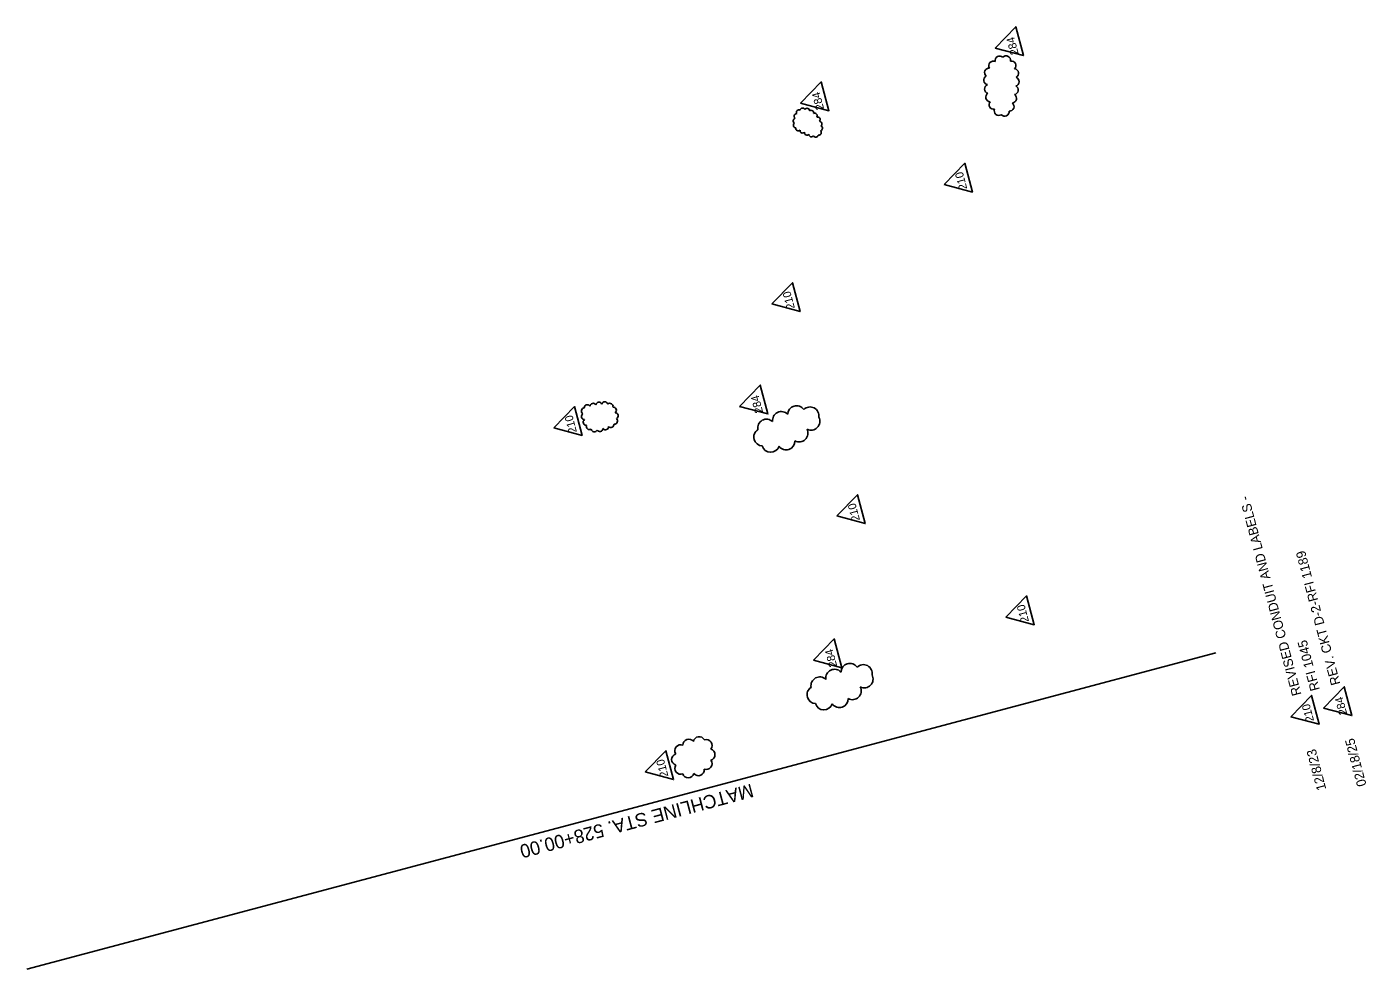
# Model space of a CAD drawing. Extents: x 930124 to 931186, y 628803 to 630086.
# Drawn here: x 930394 to 931186, y 628803 to 629360 of the extents above; entities that cross this region are included whole.
import ezdxf

# ---------------------------------------------------------------- set-up
doc = ezdxf.new("R2010")
doc.units = 0
for name, color, linetype in [('Cloud_dp', 7, 'Continuous'), ('MatchLines_dp', 7, 'Continuous'), ('TextMinor', 7, 'Continuous')]:
    doc.layers.add(name, color=color, linetype=linetype)

msp = doc.modelspace()

# ---------------------------------------------------------------- linework, layer by layer
at = {"layer": 'Cloud_dp'}
for points in [[(930966.84, 629347.6), (930983.6, 629343.14), (930979.07, 629360.19)], [(930851.74, 629315.02), (930868.49, 629310.55), (930863.96, 629327.61)], [(930936.68, 629266.85), (930953.44, 629262.39), (930948.9, 629279.45)], [(930834.69, 629196.2), (930851.44, 629191.74), (930846.91, 629208.8)], [(930815.64, 629135.59), (930832.39, 629131.13), (930827.86, 629148.18)], [(930705.73, 629122.9), (930722.49, 629118.44), (930717.95, 629135.5)], [(930873.21, 629070.79), (930889.97, 629066.32), (930885.43, 629083.38)], [(930973.23, 629010.87), (930989.98, 629006.4), (930985.45, 629023.46)], [(930859.46, 628985.41), (930876.22, 628980.95), (930871.68, 628998)], [(931141.9, 628952.04), (931158.66, 628947.58), (931154.12, 628964.64)], [(931161.19, 628957.17), (931177.94, 628952.71), (931173.41, 628969.76)], [(930759.86, 628919.33), (930776.62, 628914.86), (930772.08, 628931.92)]]:
    msp.add_lwpolyline(points, close=True, dxfattribs=at)
for centre, radius, start, end in [((930965.83, 629337.18), 2.69, 65.81449, 210.81449), ((930969.56, 629340.2), 2.69, 47.02622, 192.02622), ((930973.34, 629340.3), 2.69, 351.17918, 136.17918), ((930976.48, 629337.25), 2.69, 315.47406, 100.47406), ((930962.8, 629328.61), 2.69, 115.67642, 260.67642), ((930963.33, 629333.12), 2.69, 85.90866, 230.90866), ((930978.03, 629332.7), 2.69, 297.05766, 82.05766), ((930978.36, 629327.77), 2.69, 285.53496, 70.53496), ((930963.28, 629323.43), 2.69, 109.9098, 254.9098), ((930977.87, 629322.77), 2.69, 278.3399, 63.3399), ((930964.05, 629318.58), 2.69, 123.04285, 268.04285), ((930965.96, 629314.1), 2.69, 138.15829, 283.15829), ((930975.34, 629313.05), 2.69, 265.6604, 50.6604), ((930976.87, 629317.81), 2.69, 273.85274, 58.85274), ((930848.86, 629304.56), 1.51, 99.66415, 244.66415), ((930849.47, 629307.29), 1.51, 90.23348, 235.23348), ((930850.78, 629309.54), 1.51, 64.25659, 209.25659), ((930852.93, 629310.64), 1.51, 25.19628, 170.19628), ((930855.55, 629310.45), 1.51, 1.35126, 146.35126), ((930858.01, 629309.31), 1.51, 343.81258, 128.81258), ((930860.11, 629307.52), 1.51, 330.43389, 115.43389), ((930861.78, 629305.31), 1.51, 318.65228, 103.65228), ((930969.06, 629310.45), 2.69, 157.53748, 302.53748), ((930972.48, 629310.01), 2.69, 222.67057, 7.67057), ((930848.98, 629301.89), 1.51, 120.6446, 265.6446), ((930850.35, 629300.11), 1.51, 169.55406, 314.55406), ((930852.91, 629298.84), 1.51, 172.8068, 317.8068), ((930855.53, 629297.64), 1.51, 172.84611, 317.84611), ((930862.53, 629297.6), 1.51, 259.199, 44.199), ((930862.87, 629302.8), 1.51, 303.2417, 88.2417), ((930863.2, 629300.1), 1.51, 285.88168, 70.88168), ((930858.17, 629296.61), 1.51, 179.33238, 324.33238), ((930860.76, 629296.37), 1.51, 205.1875, 350.1875), ((930723.9, 629132.9), 1.87, 96.65996, 241.65996), ((930723.96, 629129.65), 1.87, 120.40329, 265.40329), ((930725.56, 629134.69), 1.87, 32.99519, 177.99519), ((930728.98, 629135.57), 1.87, 30.58908, 175.58908), ((930732.44, 629136.21), 1.87, 25.45378, 170.45378), ((930735.9, 629136.44), 1.87, 17.07381, 162.07381), ((930738.93, 629135.59), 1.87, 346.88986, 131.88986), ((930740.9, 629133.31), 1.87, 309.55427, 94.55427), ((930741.94, 629130), 1.87, 300.35633, 85.35633), ((930840.37, 629127.34), 5.21, 43.31257, 188.31257), ((930849.37, 629130.82), 5.21, 33.91184, 178.91184), ((930857.39, 629130.06), 5.21, 350.30948, 135.30948), ((930724.99, 629126.34), 1.87, 129.1717, 274.1717), ((930726.84, 629123.72), 1.87, 156.12895, 301.12895), ((930736.24, 629123.63), 1.87, 219.62405, 4.62405), ((930739.53, 629124.99), 1.87, 220.2265, 5.2265), ((930741.63, 629127.01), 1.87, 262.67969, 47.67969), ((930831.6, 629122.83), 5.21, 46.10802, 191.10802), ((930857.93, 629126.73), 5.21, 243.02408, 28.02408), ((930729.65, 629122.43), 1.87, 189.46548, 334.46548), ((930732.94, 629122.58), 1.87, 210.79964, 355.79964), ((930829.28, 629117.44), 5.21, 122.47753, 267.47753), ((930843.2, 629115.09), 5.21, 216.02366, 1.02366), ((930850.9, 629119.77), 5.21, 241.49045, 26.49045), ((930834.05, 629113.7), 5.21, 196.32715, 341.32715), ((930880.88, 628978.36), 5.21, 33.91184, 178.91184), ((930888.91, 628977.6), 5.21, 350.30948, 135.30948), ((930863.11, 628970.37), 5.21, 46.10802, 191.10802), ((930871.88, 628974.88), 5.21, 43.31257, 188.31257), ((930889.44, 628974.28), 5.21, 243.02408, 28.02408), ((930860.79, 628964.98), 5.21, 122.47753, 267.47753), ((930882.41, 628967.31), 5.21, 241.49045, 26.49045), ((930865.56, 628961.24), 5.21, 196.32715, 341.32715), ((930874.72, 628962.64), 5.21, 216.02366, 1.02366), ((930780.75, 628931.95), 3.47, 68.46599, 213.46599), ((930785.5, 628935.25), 3.47, 36.09124, 181.09124), ((930791.74, 628936.76), 3.47, 26.21778, 171.21778), ((930795.92, 628934.99), 3.47, 322.74245, 107.74245), ((930797.64, 628929.57), 3.47, 287.59727, 72.59727), ((930778.94, 628926.73), 3.47, 108.09552, 253.09552), ((930795.89, 628924.21), 3.47, 251.06604, 36.06604), ((930780.8, 628921.46), 3.47, 145.8684, 290.8684), ((930785.33, 628919.32), 3.47, 198.51028, 343.51028), ((930791.3, 628920.59), 3.47, 220.57779, 5.57779)]:
    msp.add_arc(centre, radius, start, end, dxfattribs=at)
at = {"layer": 'MatchLines_dp'}
msp.add_lwpolyline([(931097.53, 628989.72), (930741.83, 628895.14), (930393.92, 628802.63)], dxfattribs=at)

# ---------------------------------------------------------------- texts
at = {"layer": 'Cloud_dp'}
for s, p in [('284', (930980.81, 629344.25)), ('284', (930865.7, 629311.66)), ('210', (930950.4, 629264.44)), ('210', (930848.4, 629193.79)), ('284', (930829.6, 629132.24)), ('210', (930719.45, 629120.49)), ('210', (930886.93, 629068.37)), ('210', (930986.94, 629008.45)), ('284', (930873.43, 628982.06)), ('210', (931155.62, 628949.63)), ('284', (931175.15, 628953.82)), ('210', (930773.58, 628916.91))]:
    msp.add_text(s, height=4.799, rotation=104.89046, dxfattribs=at).set_placement(p)
at = {"layer": 'MatchLines_dp'}
msp.add_text('MATCHLINE STA. 528+00.00', height=8, rotation=194.89045, dxfattribs=at).set_placement((930822.6, 628912.48))
at = {"layer": 'TextMinor'}
for s, p in [('REVISED CONDUIT AND LABELS - ', (931148.14, 628965.21)), ('REV. CKT D-2-RFI 1189', (931171.19, 628971.48)), ('RFI 1045', (931158.97, 628968.09)), ('12/8/23', (931162.84, 628909.17)), ('02/18/25', (931186.65, 628911.55))]:
    msp.add_text(s, height=5.6, rotation=104.89045, dxfattribs=at).set_placement(p)

doc.saveas('drawing.dxf')
